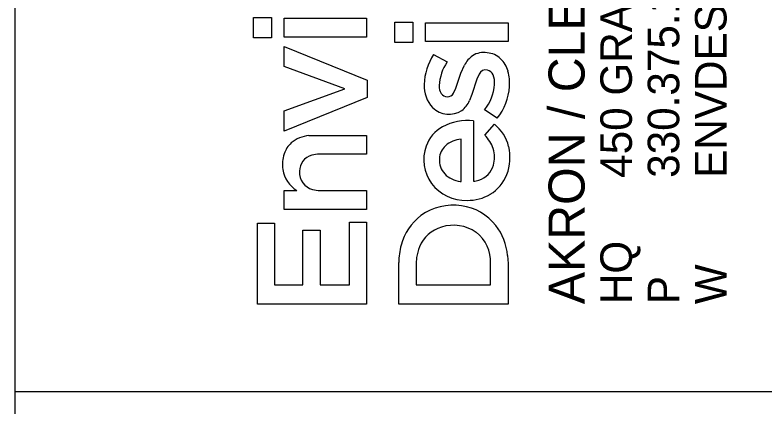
# Model space of a CAD drawing. Extents: x -0.4 to 34, y 0 to 22.
# Drawn here: x 32 to 33.185, y 2.476 to 3.094 of the extents above; entities that cross this region are included whole.
import ezdxf

# ---------------------------------------------------------------- set-up
doc = ezdxf.new("R2010")
doc.units = 0
doc.layers.add('SH_Cut_Line', color=7, linetype='Continuous')
doc.layers.add('SH_Data', color=7, linetype='Continuous')

msp = doc.modelspace()

# ---------------------------------------------------------------- linework, layer by layer
at = {"layer": 'SH_Cut_Line'}
for p, q in [((32.3771, 3.0582), (32.3771, 3.0903)), ((32.3771, 3.0903), (32.4054, 3.0903)), ((32.4054, 3.0903), (32.4054, 3.0582)), ((32.4254, 3.0594), (32.4254, 3.0893)), ((32.4254, 3.0893), (32.5557, 3.0893)), ((32.5557, 3.0893), (32.5557, 3.0594)), ((32.6005, 3.0511), (32.6005, 3.0832)), ((32.6005, 3.0832), (32.6289, 3.0832)), ((32.6289, 3.0832), (32.6289, 3.0511)), ((32.6489, 3.0523), (32.6489, 3.0822)), ((32.6489, 3.0822), (32.7792, 3.0822)), ((32.7792, 3.0822), (32.7792, 3.0523)), ((32.4054, 3.0582), (32.3771, 3.0582)), ((32.5557, 3.0594), (32.4254, 3.0594)), ((32.6289, 3.0511), (32.6005, 3.0511)), ((32.7792, 3.0523), (32.6489, 3.0523)), ((32.4254, 3.0133), (32.4254, 3.0446)), ((32.4254, 3.0446), (32.5567, 2.9913)), ((32.6615, 3.0321), (32.6827, 3.0203)), ((32.5212, 2.978), (32.4254, 3.0133)), ((32.7048, 3.0026), (32.7104, 3.0153)), ((32.6967, 2.9787), (32.7048, 3.0026)), ((32.7334, 3.001), (32.7298, 2.9933)), ((32.5567, 2.9913), (32.5567, 2.9644)), ((32.7298, 2.9933), (32.7221, 2.9688)), ((32.4254, 2.9429), (32.5212, 2.978)), ((32.693, 2.9712), (32.6967, 2.9787)), ((32.5567, 2.9644), (32.4254, 2.9109)), ((32.7221, 2.9688), (32.7182, 2.9592)), ((32.4254, 2.9109), (32.4254, 2.9429)), ((32.7621, 2.9314), (32.742, 2.9447)), ((32.7245, 2.9275), (32.7246, 2.8319)), ((32.7423, 2.9046), (32.7577, 2.922)), ((32.4644, 2.904), (32.4729, 2.9044)), ((32.4729, 2.9044), (32.5557, 2.9044)), ((32.5557, 2.9044), (32.5557, 2.8746)), ((32.7049, 2.8318), (32.7049, 2.8983)), ((32.5557, 2.8746), (32.4814, 2.8746)), ((32.7036, 2.8317), (32.7049, 2.8318)), ((32.4254, 2.7875), (32.4254, 2.8173)), ((32.4254, 2.8173), (32.4455, 2.8173)), ((32.4822, 2.8173), (32.5557, 2.8173)), ((32.5557, 2.8173), (32.5557, 2.7876)), ((32.5557, 2.7876), (32.4254, 2.7875)), ((32.383, 2.6379), (32.383, 2.766)), ((32.383, 2.766), (32.4101, 2.766)), ((32.4101, 2.766), (32.4101, 2.6683)), ((32.5286, 2.6683), (32.5286, 2.7672)), ((32.5286, 2.7672), (32.5557, 2.7672)), ((32.5557, 2.7672), (32.5557, 2.6379)), ((32.455, 2.6683), (32.455, 2.7549)), ((32.455, 2.7549), (32.4822, 2.7549)), ((32.4822, 2.7549), (32.4822, 2.6683)), ((32.7785, 2.715), (32.7792, 2.7021)), ((32.6064, 2.638), (32.6064, 2.704)), ((32.6347, 2.7118), (32.6341, 2.7023)), ((32.6341, 2.7023), (32.6341, 2.6684)), ((32.7515, 2.6683), (32.7515, 2.7024)), ((32.7792, 2.7021), (32.7792, 2.638)), ((32.4101, 2.6683), (32.455, 2.6683)), ((32.4822, 2.6683), (32.5286, 2.6683)), ((32.6341, 2.6684), (32.7515, 2.6683)), ((32.5557, 2.6379), (32.383, 2.6379)), ((32.7792, 2.638), (32.6064, 2.638))]:
    msp.add_line(p, q, dxfattribs=at)
for points in [[(32.3771, 3.0582), (32.3771, 3.0903), (32.4054, 3.0903), (32.4054, 3.0582)], [(32.4254, 3.0594), (32.4254, 3.0893), (32.5557, 3.0893), (32.5557, 3.0594)], [(32.6005, 3.0511), (32.6005, 3.0832), (32.6289, 3.0832), (32.6289, 3.0511)], [(32.6489, 3.0523), (32.6489, 3.0822), (32.7792, 3.0822), (32.7792, 3.0523)], [(32.4254, 2.9109), (32.4254, 2.9429), (32.5212, 2.978), (32.4254, 3.0133), (32.4254, 3.0446), (32.5567, 2.9913), (32.5567, 2.9644)], [(32.383, 2.6379), (32.383, 2.766), (32.4101, 2.766), (32.4101, 2.6683), (32.455, 2.6683), (32.455, 2.7549), (32.4822, 2.7549), (32.4822, 2.6683), (32.5286, 2.6683), (32.5286, 2.7672), (32.5557, 2.7672), (32.5557, 2.6379)]]:
    msp.add_lwpolyline(points, close=True, dxfattribs=at)
for points in [[(32.6615, 3.0321), (32.6827, 3.0203)], [(32.693, 2.9712), (32.6967, 2.9787), (32.7048, 3.0026), (32.7104, 3.0153)], [(32.7334, 3.001), (32.7298, 2.9933), (32.7221, 2.9688), (32.7182, 2.9592)], [(32.7621, 2.9314), (32.742, 2.9447)], [(32.7245, 2.9275), (32.7246, 2.8319)], [(32.7423, 2.9046), (32.7577, 2.922)], [(32.4644, 2.904), (32.4729, 2.9044), (32.5557, 2.9044), (32.5557, 2.8746), (32.4814, 2.8746)], [(32.7036, 2.8317), (32.7049, 2.8318), (32.7049, 2.8983)], [(32.4254, 2.7875), (32.4254, 2.8173), (32.4455, 2.8173)], [(32.4822, 2.8173), (32.5557, 2.8173), (32.5557, 2.7876), (32.4254, 2.7875)], [(32.7785, 2.715), (32.7792, 2.7021), (32.7792, 2.638), (32.6064, 2.638)], [(32.6064, 2.638), (32.6064, 2.704)], [(32.6347, 2.7118), (32.6341, 2.7023), (32.6341, 2.6684), (32.7515, 2.6683), (32.7515, 2.7024)]]:
    msp.add_lwpolyline(points, dxfattribs=at)
for centre, radius, start, end in [((32.7406, 3.0026), 0.0326, 80.1719, 122.5197), ((32.7406, 3.0026), 0.0326, 80.1719, 122.5197), ((32.7428, 2.9982), 0.0367, 47.7934, 84.6892), ((32.7428, 2.9982), 0.0367, 47.7934, 84.6892), ((32.7364, 2.9826), 0.0897, 146.531, 178.7571), ((32.7364, 2.9826), 0.0897, 146.531, 178.7571), ((32.7466, 2.9971), 0.0405, 125.5118, 153.4159), ((32.7466, 2.9971), 0.0405, 125.5118, 153.4159), ((32.7379, 2.9946), 0.0427, 14.9966, 46.2063), ((32.7379, 2.9946), 0.0427, 14.9966, 46.2063), ((32.7452, 2.9789), 0.0749, 146.5112, 176.9101), ((32.7452, 2.9789), 0.0749, 146.5112, 176.9101), ((32.7438, 2.9963), 0.0114, 76.6609, 155.7053), ((32.7438, 2.9963), 0.0114, 76.6609, 155.7053), ((32.744, 2.9951), 0.0126, 21.5098, 78.5262), ((32.744, 2.9951), 0.0126, 21.5098, 78.5262), ((32.7259, 2.9877), 0.0321, 354.5726, 22.068), ((32.7259, 2.9877), 0.0321, 354.5726, 22.068), ((32.7104, 2.9867), 0.0712, 355.8306, 15.3914), ((32.7104, 2.9867), 0.0712, 355.8306, 15.3914), ((32.6967, 2.9824), 0.0501, 177.5366, 222.7932), ((32.6967, 2.9824), 0.0501, 177.5366, 222.7932), ((32.6931, 2.9823), 0.0228, 178.4747, 211.0868), ((32.6931, 2.9823), 0.0228, 178.4747, 211.0868), ((32.6825, 2.9915), 0.0757, 321.811, 354.7969), ((32.6825, 2.9915), 0.0757, 321.811, 354.7969), ((32.6895, 2.9882), 0.0922, 321.9777, 355.8738), ((32.6895, 2.9882), 0.0922, 321.9777, 355.8738), ((32.6833, 2.9767), 0.0115, 212.2368, 268.3777), ((32.6833, 2.9767), 0.0115, 212.2368, 268.3777), ((32.6834, 2.9759), 0.0107, 267.716, 333.7337), ((32.6834, 2.9759), 0.0107, 267.716, 333.7337), ((32.681, 2.9758), 0.0408, 308.0877, 335.9874), ((32.681, 2.9758), 0.0408, 308.0877, 335.9874), ((32.686, 2.9753), 0.0375, 225.9854, 302.4797), ((32.686, 2.9753), 0.0375, 225.9854, 302.4797), ((32.7152, 2.8441), 0.0838, 83.615, 118.2876), ((32.7152, 2.8441), 0.0838, 83.615, 118.2876), ((32.7024, 2.8691), 0.0558, 118.8308, 160.6244), ((32.7024, 2.8691), 0.0558, 118.8308, 160.6244), ((32.7174, 2.8717), 0.0644, 13.5336, 51.3615), ((32.7174, 2.8717), 0.0644, 13.5336, 51.3615), ((32.4687, 2.8543), 0.0499, 94.9696, 130.2225), ((32.4687, 2.8543), 0.0499, 94.9696, 130.2225), ((32.7038, 2.8656), 0.0549, 19.0357, 45.4406), ((32.7038, 2.8656), 0.0549, 19.0357, 45.4406), ((32.4635, 2.8626), 0.0402, 132.2219, 161.6818), ((32.4635, 2.8626), 0.0402, 132.2219, 161.6818), ((32.7079, 2.8561), 0.0424, 94.008, 130.8817), ((32.7079, 2.8561), 0.0424, 94.008, 130.8817), ((32.7104, 2.8661), 0.0644, 160.5201, 215.7831), ((32.7104, 2.8661), 0.0644, 160.5201, 215.7831), ((32.7005, 2.8663), 0.0298, 132.9851, 177.179), ((32.7005, 2.8663), 0.0298, 132.9851, 177.179), ((32.7107, 2.8697), 0.047, 344.6059, 17.007), ((32.7107, 2.8697), 0.047, 344.6059, 17.007), ((32.7064, 2.8692), 0.0758, 339.3542, 13.3785), ((32.7064, 2.8692), 0.0758, 339.3542, 13.3785), ((32.4787, 2.8582), 0.056, 162.2736, 187.7919), ((32.4787, 2.8582), 0.056, 162.2736, 187.7919), ((32.4748, 2.8487), 0.025, 103.6865, 182.2187), ((32.4748, 2.8487), 0.025, 103.6865, 182.2187), ((32.4811, 2.8286), 0.046, 89.6049, 105.3284), ((32.4811, 2.8286), 0.046, 89.6049, 105.3284), ((32.7017, 2.865), 0.0311, 175.0013, 223.283), ((32.7017, 2.865), 0.0311, 175.0013, 223.283), ((32.7224, 2.8671), 0.035, 288.0077, 343.5508), ((32.7224, 2.8671), 0.035, 288.0077, 343.5508), ((32.4703, 2.858), 0.0476, 188.962, 238.7037), ((32.4703, 2.858), 0.0476, 188.962, 238.7037), ((32.4773, 2.8456), 0.0276, 175.5854, 255.1439), ((32.4773, 2.8456), 0.0276, 175.5854, 255.1439), ((32.7089, 2.8736), 0.0423, 225.0619, 262.7974), ((32.7089, 2.8736), 0.0423, 225.0619, 262.7974), ((32.7247, 2.8522), 0.0202, 269.7003, 294.8711), ((32.7247, 2.8522), 0.0202, 269.7003, 294.8711), ((32.7189, 2.8652), 0.0626, 300.9427, 338.7323), ((32.7189, 2.8652), 0.0626, 300.9427, 338.7323), ((32.7125, 2.8705), 0.0687, 217.7452, 271.6543), ((32.7125, 2.8705), 0.0687, 217.7452, 271.6543), ((32.4818, 2.8595), 0.0422, 254.0916, 270.5284), ((32.4818, 2.8595), 0.0422, 254.0916, 270.5284), ((32.7155, 2.8724), 0.0706, 269.2048, 300.3341), ((32.7155, 2.8724), 0.0706, 269.2048, 300.3341), ((32.6923, 2.7079), 0.0864, 81.194, 125.9984), ((32.6923, 2.7079), 0.0864, 81.194, 125.9984), ((32.6946, 2.7113), 0.0827, 37.8521, 82.402), ((32.6946, 2.7113), 0.0827, 37.8521, 82.402), ((32.6939, 2.7089), 0.0865, 127.2362, 165.148), ((32.6939, 2.7089), 0.0865, 127.2362, 165.148), ((32.6928, 2.6986), 0.0639, 55.6727, 107.2093), ((32.6928, 2.6986), 0.0639, 55.6727, 107.2093), ((32.6859, 2.7057), 0.0931, 5.7333, 37.304), ((32.6859, 2.7057), 0.0931, 5.7333, 37.304), ((32.6889, 2.7078), 0.054, 106.1881, 157.3861), ((32.6889, 2.7078), 0.054, 106.1881, 157.3861), ((32.6929, 2.705), 0.0587, 357.4662, 52.2665), ((32.6929, 2.705), 0.0587, 357.4662, 52.2665), ((32.7143, 2.7028), 0.1078, 164.7861, 179.3704), ((32.7143, 2.7028), 0.1078, 164.7861, 179.3704), ((32.6983, 2.7039), 0.0641, 157.3571, 172.9275), ((32.6983, 2.7039), 0.0641, 157.3571, 172.9275)]:
    msp.add_arc(centre, radius, start, end, dxfattribs=at)
at = {"layer": 'SH_Data'}
for p, q in [((32, 0.5), (32, 21.5)), ((32, 2.5), (33.5, 2.5))]:
    msp.add_line(p, q, dxfattribs=at)

# ---------------------------------------------------------------- texts
at = {"layer": 'SH_Cut_Line'}
for s, height, p in [('450 GRANT ST., AKRON, OH  44311', 0.049846, (32.9749, 2.8374)), ('AKRON / CLEVELAND / COLUMBUS', 0.056969, (32.9001, 2.638)), ('ENVDESIGNGROUP.COM', 0.049846, (33.1244, 2.8374)), ('330.375.1390', 0.049846, (33.0497, 2.8374)), ('HQ ', 0.04985, (32.9749, 2.638)), ('W', 0.0498, (33.1244, 2.638)), ('P', 0.0498, (33.0497, 2.638))]:
    msp.add_text(s, height=height, rotation=90, dxfattribs=at).set_placement(p)

doc.saveas('drawing.dxf')
